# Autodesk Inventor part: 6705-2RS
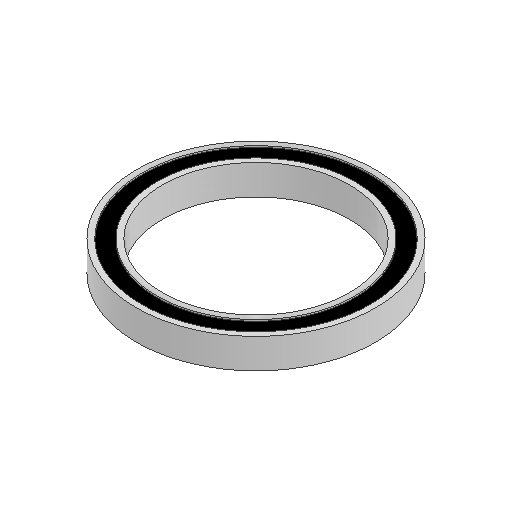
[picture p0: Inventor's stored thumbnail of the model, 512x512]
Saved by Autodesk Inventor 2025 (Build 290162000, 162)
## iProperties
Created: 2025-06
Part Number: 6705-2RS
Material: Generico
Document SubType Name: Modeling
Designer: R5800u
Density: 1 g/cm^3
Appearance: Default
Author: R5800u
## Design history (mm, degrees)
sketch "Schizzo1"
  geometry: C1 r 12.5 at (0, 0); C2 r 16 at (0, 0); 1 further point
  constraints: 2 centre point, 2 coincident
  dimensions: "d0" = 25 diameter of C1; "d1" = 32 diameter of C2
extrude "Estrusione1" new body sketch "Schizzo1" stored distance "d2" = 4; taper "d3" = 0 deg
sketch "Schizzo2"
  geometry: C1 r 13.25 at (0, 0); C2 r 15.25 at (0, 0); 1 further point
  constraints: 2 centre point, 2 coincident
  dimensions: "d4" = 26.5 diameter of C1; "d5" = 30.5 diameter of C2
extrude "Estrusione2" cut sketch "Schizzo2" distance "d6" = 0.2; taper "d7" = 0 deg
mirror "Speculare1"
node "Solido1"
